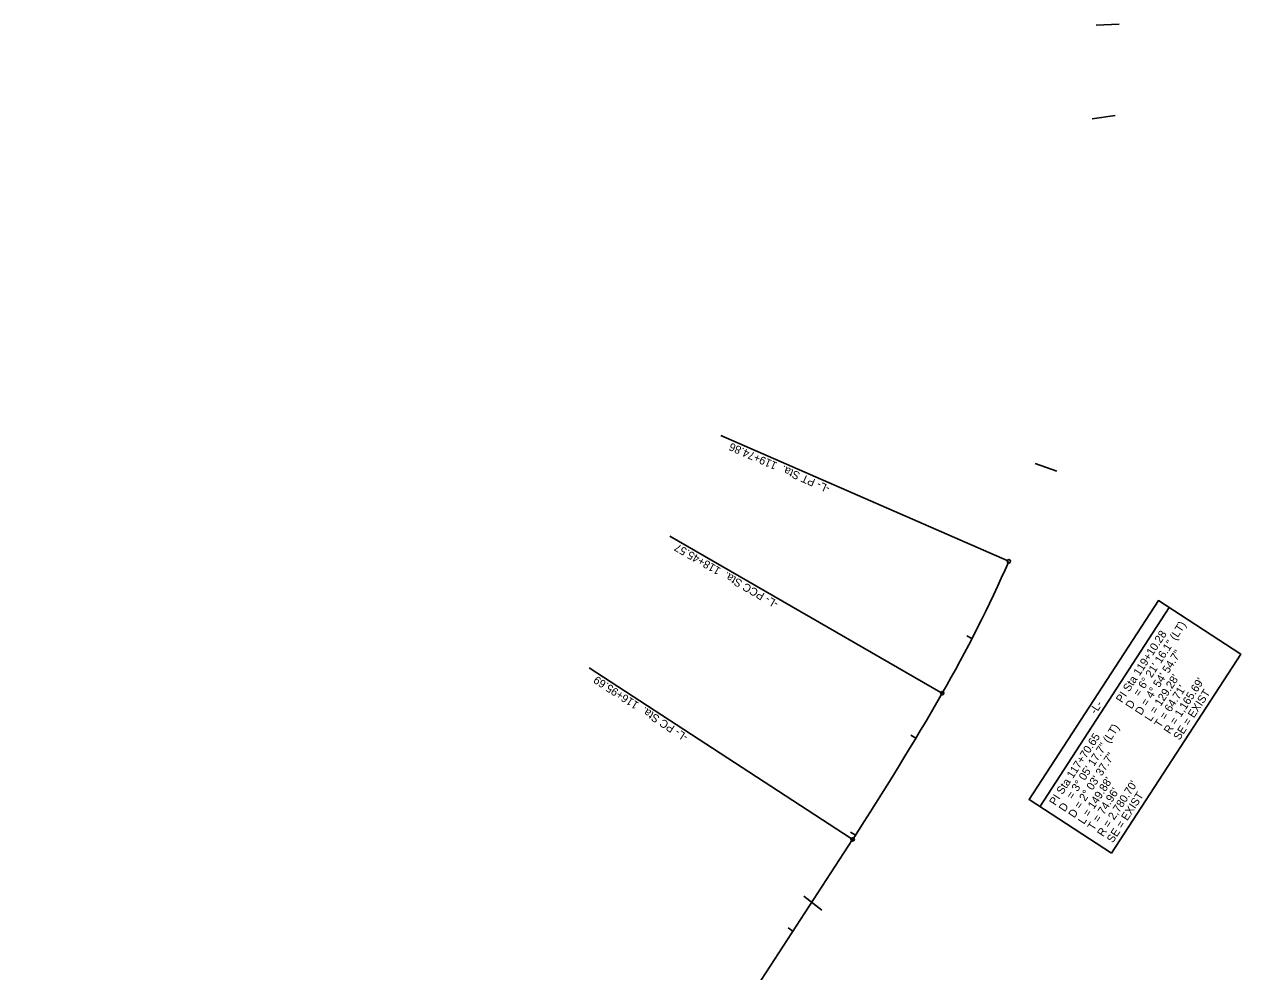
# Model space of a CAD drawing. Extents: x 1019959 to 1023888, y 635993 to 644996.
# Drawn here: x 1022816 to 1023880, y 644168 to 644996 of the extents above; entities that cross this region are included whole.
import ezdxf

# ---------------------------------------------------------------- set-up
doc = ezdxf.new("R2010")
doc.units = 0
for name, color, linetype in [('COGO Default Point Elevation', 7, 'Continuous'), ('Exist Roads EOT', 7, 'Continuous'), ('Exist Structure Minor Pipes CMP 18 Inch Cogo Number', 7, 'Continuous'), ('Exist Structure Minor Pipes CMP 24 Inch Cogo Number', 7, 'Continuous'), ('Exist Utilities Power Pole CELL', 7, 'Continuous'), ('Exist Utilities Power Pole Cogo Elevation', 7, 'Continuous')]:
    doc.layers.add(name, color=color, linetype=linetype)

msp = doc.modelspace()

# ---------------------------------------------------------------- linework, layer by layer
at = {"layer": 'COGO Default Point Elevation'}
for p, q in [((1023644.9, 644459.1), (1023640.5, 644461.4)), ((1023595.8, 644372), (1023591.5, 644374.6)), ((1023542.9, 644287.2), (1023538.7, 644289.9)), ((1023488.3, 644203.3), (1023484.2, 644206.1))]:
    msp.add_line(p, q, dxfattribs=at)
at = {"layer": 'Exist Roads EOT'}
for p, q in [((1023675.7, 644527.3), (1023425.1, 644636.8)), ((1023617.6, 644412.1), (1023380.6, 644548.7)), ((1023539.3, 644284.4), (1023310.1, 644433.5))]:
    msp.add_line(p, q, dxfattribs=at)
for centre in [(1023677.1, 644526.7), (1023618.9, 644411.3), (1023540.5, 644283.5)]:
    msp.add_circle(centre, 1.5, dxfattribs=at)
at = {"layer": 'Exist Structure Minor Pipes CMP 18 Inch Cogo Number'}
msp.add_line((1022815.8, 643169.9), (1023540.5, 644283.5), dxfattribs=at)
for centre, radius, start, end in [((1022609, 644993.6), 1165.7, 330.0323, 336.3868), ((1021209.9, 645800.3), 2780.7, 326.9441, 330.0323)]:
    msp.add_arc(centre, radius, start, end, dxfattribs=at)
at = {"layer": 'Exist Structure Minor Pipes CMP 24 Inch Cogo Number'}
for p, q in [((1023773.7, 644996.4), (1023753.5, 644995.7)), ((1023770.3, 644916.7), (1023750, 644913.8)), ((1023700.2, 644612.4), (1023719.2, 644605.7)), ((1023497.7, 644233.8), (1023513.4, 644221.7))]:
    msp.add_line(p, q, dxfattribs=at)
at = {"layer": 'Exist Utilities Power Pole CELL'}
msp.add_line((1022815.8, 643169.9), (1023540.5, 644283.5), dxfattribs=at)
for centre, radius, start, end in [((1022609, 644993.6), 1165.7, 330.0323, 336.3868), ((1021209.9, 645800.3), 2780.7, 326.9441, 330.0323)]:
    msp.add_arc(centre, radius, start, end, dxfattribs=at)
at = {"layer": 'Exist Utilities Power Pole Cogo Elevation'}
msp.add_line((1023704.4, 644312.1), (1023817.5, 644486.2), dxfattribs=at)
msp.add_lwpolyline([(1023766.9, 644271.5), (1023880, 644445.6), (1023808, 644492.4), (1023694.9, 644318.3)], close=True, dxfattribs=at)

# ---------------------------------------------------------------- texts
at = {"layer": 'Exist Roads EOT'}
for s, rotation, p in [('-L- PT Sta.  119+74.86', 156.3868, (1023521.3, 644592.6)), ('-L- PCC Sta.  118+45.57', 150.0323, (1023476.2, 644491.3)), ('-L- PC Sta.  116+95.69', 146.9441, (1023397.2, 644374.5))]:
    msp.add_text(s, height=7, rotation=rotation, dxfattribs=at).set_placement(p)
at = {"layer": 'Exist Utilities Power Pole Cogo Elevation'}
for s, p in [('= 6%%d 21\' 16.1" (LT)', (1023791.3, 644407.9)), ('PI Sta 119+10.28', (1023776.1, 644402.4)), ('D = 4%%d 54\' 54.7"', (1023792.9, 644391.5)), ("L = 129.28'", (1023801.3, 644386.1)), ("T = 64.71'", (1023809.7, 644380.6)), ("R = 1,165.69'", (1023818, 644375.2)), ('SE = EXIST', (1023826.4, 644369.7)), ('-L-', (1023753.2, 644392.5)), ('D', (1023784.5, 644397)), ('PI Sta 117+70.65', (1023717.8, 644312.6)), ('= 3%%d 05\' 17.7" (LT)', (1023732.9, 644318.1)), ('D = 2%%d 03\' 37.7"', (1023734.5, 644301.7)), ("L = 149.88'", (1023742.9, 644296.2)), ("R = 2,780.70'", (1023759.7, 644285.3)), ("T = 74.96'", (1023751.3, 644290.8)), ('SE = EXIST', (1023768.1, 644279.9)), ('D', (1023726.1, 644307.1))]:
    msp.add_text(s, height=7, rotation=56.9906, dxfattribs=at).set_placement(p)

doc.saveas('drawing.dxf')
